Omron CX-Programmer project NuevoProyecto (CX-Programmer 9.50)

# PLC NuevoPLC1: CQM1 CPU21

## Program P1_5 (no task)
Local symbols
B 100.00 BOOL
FSp 15.00 BOOL
p 0.00 BOOL

### Section Sección1_Programa_principal

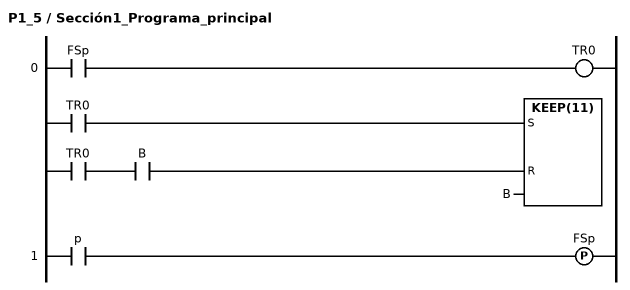
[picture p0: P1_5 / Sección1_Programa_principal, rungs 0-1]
; rung 0
LD FSp
OUT TR0
LD TR0
AND B
KEEP(11) B
; rung 1
LD p
DIFU(13) FSp

### Section END
; rung 0
END(01)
